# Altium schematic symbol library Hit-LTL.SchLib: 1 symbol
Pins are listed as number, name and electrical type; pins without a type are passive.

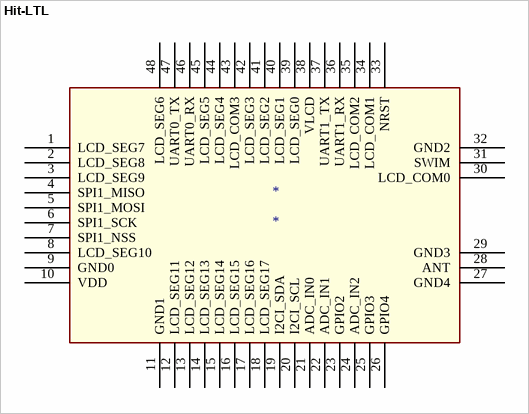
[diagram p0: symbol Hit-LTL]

## Hit-LTL
designator *
pins: 1 LCD_SEG7, 2 LCD_SEG8, 3 LCD_SEG9, 4 SPI1_MISO, 5 SPI1_MOSI, 6 SPI1_SCK, 7 SPI1_NSS, 8 LCD_SEG10, 9 GND0, 10 VDD, 11 GND1, 12 LCD_SEG11, 13 LCD_SEG12, 14 LCD_SEG13, 15 LCD_SEG14, 16 LCD_SEG15, 17 LCD_SEG16, 18 LCD_SEG17, 19 I2CI_SDA, 20 I2CI_SCL, 21 ADC_IN0, 22 ADC_IN1, 23 GPIO2, 24 ADC_IN2, 25 GPIO3, 26 GPIO4, 27 GND4, 28 ANT, 29 GND3, 30 LCD_COM0, 31 SWIM, 32 GND2, 33 NRST, 34 LCD_COM1, 35 LCD_COM2, 36 UART1_RX, 37 UART1_TX, 38 VLCD, 39 LCD_SEG0, 40 LCD_SEG1, 41 LCD_SEG2, 42 LCD_SEG3, 43 LCD_COM3, 44 LCD_SEG4, 45 LCD_SEG5, 46 UART0_RX, 47 UART0_TX, 48 LCD_SEG6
